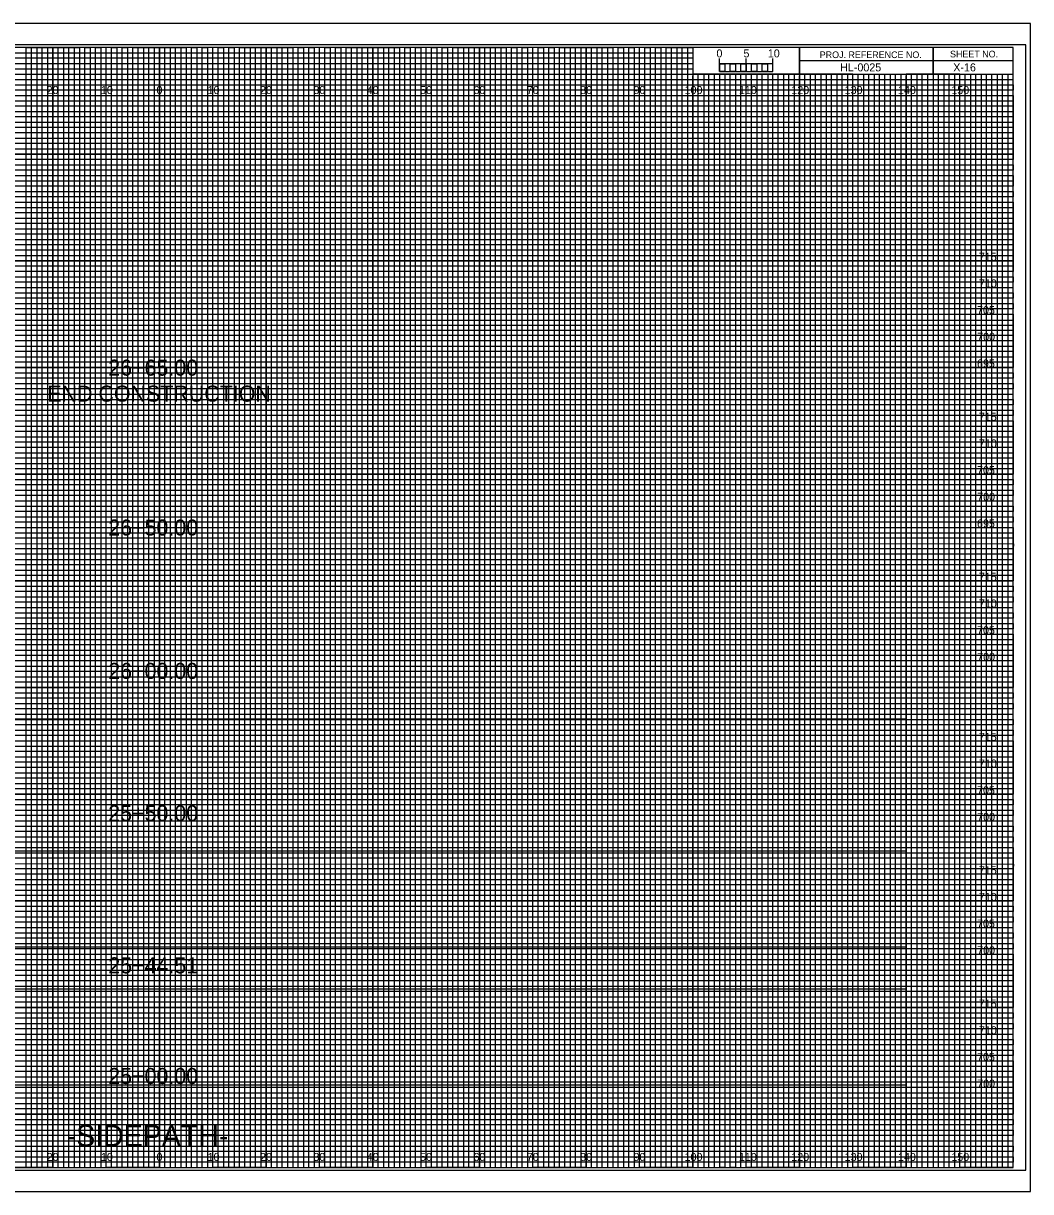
# Model space of a CAD drawing. Extents: x -13 to 323, y -5 to 215.
# Drawn here: x 134.5 to 323.3, y -4.5 to 214.5 of the extents above; entities that cross this region are included whole.
import ezdxf

# ---------------------------------------------------------------- set-up
doc = ezdxf.new("R2010")
doc.units = 0
for name, color, linetype in [('Prop XS Alignment Label', 7, 'Continuous'), ('Prop XS Bar Scale Labels', 7, 'Continuous'), ('Prop XS Elevation Labels', 7, 'Continuous'), ('Prop XS Offset Labels', 7, 'Continuous'), ('Prop XS Project Number', 7, 'Continuous'), ('Prop XS Sheet Number', 7, 'Continuous'), ('Prop XS Station Labels', 7, 'Continuous'), ('Scratch_Level_3', 7, 'Continuous'), ('Sheet Cross Section CELL', 7, 'Continuous'), ('Sheet Cross Section Grid Major CELL', 7, 'Continuous'), ('Sheet Cross Section Grid Middle CELL', 7, 'Continuous'), ('Sheet Cross Section Grid Minor 1 CELL', 7, 'Continuous'), ('Sheet Cross Section Grid Minor 2 CELL', 7, 'Continuous'), ('Sheet Cross Section Scale CELL', 7, 'Continuous'), ('Sheet Cutting Line CELL', 7, 'Continuous'), ('Sheet DOT Grid CELL', 7, 'Continuous'), ('Sheet Plot Border Inside CELL', 7, 'Continuous'), ('Sheet Plot Border Outside CELL', 7, 'Continuous')]:
    doc.layers.add(name, color=color, linetype=linetype)

msp = doc.modelspace()

# ---------------------------------------------------------------- linework, layer by layer
at = {"layer": 'Scratch_Level_3'}
for points in [[(20, 84.12), (300, 84.12), (300, 66.04), (20, 66.04)], [(20, 59.39), (300, 59.39), (300, 41.31), (20, 41.31)], [(20, 33.54), (300, 33.54), (300, 15.46), (20, 15.46)]]:
    msp.add_lwpolyline(points, close=True, dxfattribs=at)
at = {"layer": 'Sheet Cross Section CELL'}
for p, q in [((305, 210), (305, 205)), ((305, 205), (305, 210)), ((280, 207.5), (280, 205)), ((320, 207.49), (280, 207.49)), ((280, 205), (320, 205))]:
    msp.add_line(p, q, dxfattribs=at)
for points in [[(320, 210), (0, 210), (0, 0), (320, 0)], [(280, 210), (260, 210), (260, 205.03), (280, 205.03)], [(320, 210), (280, 210), (280, 205), (320, 205)]]:
    msp.add_lwpolyline(points, close=True, dxfattribs=at)
at = {"layer": 'Sheet Cross Section Grid Major CELL'}
for p, q in [((150, 210), (140, 210)), ((140, 210), (140, 0)), ((150, 0), (150, 210)), ((170, 210), (160, 210)), ((160, 210), (160, 0)), ((170, 0), (170, 210)), ((190, 210), (180, 210)), ((180, 210), (180, 0)), ((190, 0), (190, 210)), ((210, 210), (200, 210)), ((200, 210), (200, 0)), ((210, 0), (210, 210)), ((230, 210), (220, 210)), ((220, 210), (220, 0)), ((230, 0), (230, 210)), ((250, 210), (240, 210)), ((240, 210), (240, 0)), ((250, 0), (250, 210)), ((260, 210), (260, 0)), ((270, 0), (270, 205)), ((290, 205), (280, 205)), ((280, 205), (280, 0)), ((290, 0), (290, 205)), ((310, 205), (300, 205)), ((300, 205), (300, 0)), ((310, 0), (310, 205)), ((140, 0), (130, 0)), ((160, 0), (150, 0)), ((180, 0), (170, 0)), ((200, 0), (190, 0)), ((220, 0), (210, 0)), ((240, 0), (230, 0)), ((260, 0), (250, 0)), ((280, 0), (270, 0)), ((300, 0), (290, 0)), ((320, 0), (310, 0)), ((320, 0), (320, 0))]:
    msp.add_line(p, q, dxfattribs=at)
for points in [[(0, 200), (320, 200), (320, 190), (0, 190)], [(0, 180), (320, 180), (320, 170), (0, 170)], [(0, 160), (320, 160), (320, 150), (0, 150)], [(0, 140), (320, 140), (320, 130), (0, 130)], [(0, 120), (320, 120), (320, 110), (0, 110)], [(0, 100), (320, 100), (320, 90), (0, 90)], [(0, 80), (320, 80), (320, 70), (0, 70)], [(0, 60), (320, 60), (320, 50), (0, 50)], [(0, 40), (320, 40), (320, 30), (0, 30)], [(0, 20), (320, 20), (320, 10), (0, 10)]]:
    msp.add_lwpolyline(points, dxfattribs=at)
at = {"layer": 'Sheet Cross Section Grid Middle CELL'}
for points in [[(125, 0), (135, 0), (135, 210), (145, 210), (145, 0), (155, 0), (155, 210), (165, 210), (165, 0), (175, 0), (175, 210), (185, 210), (185, 0), (195, 0), (195, 210), (205, 210), (205, 0), (215, 0), (215, 210), (225, 210), (225, 0), (235, 0), (235, 210), (245, 210), (245, 0), (255, 0), (255, 210), (259.93, 210), (260, 210), (260, 205), (264.99, 205), (264.99, 0), (275, 0), (275, 205), (285, 205), (285, 0), (295, 0), (295, 205), (305, 205), (305, 0), (315, 0), (315, 205)], [(0, 205), (275, 205)], [(0, 185), (320, 185), (320, 195), (0, 195)], [(0, 165), (320, 165), (320, 175), (0, 175)], [(0, 145), (320, 145), (320, 155), (0, 155)], [(0, 125), (320, 125), (320, 135), (0, 135)], [(0, 105), (320, 105), (320, 115), (0, 115)], [(0, 85), (320, 85), (320, 95), (0, 95)], [(0, 65), (320, 65), (320, 75), (0, 75)], [(0, 45), (320, 45), (320, 55), (0, 55)], [(0, 25), (320, 25), (320, 35), (0, 35)], [(0, 5), (320, 5), (320, 15), (0, 15)]]:
    msp.add_lwpolyline(points, dxfattribs=at)
at = {"layer": 'Sheet Cross Section Grid Minor 1 CELL'}
for p, q in [((0, 209), (260, 209)), ((260, 209), (260, 207.98)), ((260, 207.98), (0, 207.98)), ((0, 207), (260, 207)), ((260, 205.89), (0, 205.89)), ((260, 207), (260, 205.89)), ((0, 204), (320, 204))]:
    msp.add_line(p, q, dxfattribs=at)
for points in [[(0, 203), (270, 203), (320, 203), (320, 202), (0, 202)], [(0, 201), (320, 201), (320, 199), (0, 199)], [(0, 198), (320, 198), (320, 197), (0, 196.98)], [(0, 196), (320, 196), (320, 194), (0, 194)], [(0, 193), (320, 193), (320, 192), (0, 192)], [(0, 191), (320, 191), (320, 189), (0, 189)], [(0, 188), (320, 188), (320, 187), (0, 187)], [(0, 186), (320, 186), (320, 184), (0, 184)], [(0, 183), (320, 183), (320, 182), (0, 182)], [(0, 181), (320, 181), (320, 179), (0, 179)], [(0, 178), (320, 178), (320, 177), (0, 177)], [(0, 176), (320, 176), (320, 173.95), (320, 173), (320, 172), (0, 172)], [(0, 174), (320, 174), (320, 173), (0, 173)], [(0, 171), (320, 171), (320, 169), (0, 169.03)], [(0, 169.03), (320, 169), (320, 168), (0, 168)], [(0, 167), (320, 167), (320, 166), (0, 166)], [(0, 164), (320, 164), (320, 163), (0, 163)], [(0, 162), (320, 162), (320, 161), (0, 161)], [(-0.07, 158.89), (320, 158.89), (320, 157.88), (-0.07, 157.88)], [(0, 157), (320, 157), (320, 156), (0, 156)], [(0, 154), (320, 154), (320, 153), (0, 153)], [(0, 152), (320, 152), (320, 151), (0, 151)], [(0, 149), (320, 149), (320, 148), (0, 148)], [(0, 147), (320, 147), (320, 146), (0, 146)], [(0, 144), (320, 144), (320, 143), (0, 143)], [(0, 142), (320, 142), (320, 141), (0, 141)], [(0, 139), (320, 139), (319.99, 137.98), (0, 138)], [(0, 137), (320, 137), (320, 136), (0, 136)], [(0, 134), (320, 134), (320, 133), (0, 133)], [(0, 132), (320, 132), (320, 131), (0, 131)], [(0, 129), (320, 129), (320, 128), (0, 128)], [(0, 127), (320, 127), (320, 126), (0, 126)], [(0, 124), (320, 124), (320, 123), (0, 123)], [(0, 122), (320, 122), (320, 121), (0, 121)], [(0, 119), (320, 119), (320, 118), (0, 118)], [(0, 116.99), (320.07, 116.91), (320, 116), (0, 116)], [(0, 114), (320, 114), (320, 113), (0, 113)], [(0, 112), (320, 112), (320, 111), (0, 111)], [(0, 109), (320, 109), (320, 108), (0, 108)], [(0, 107), (320, 107), (320, 106), (0, 106)], [(0, 104), (320, 104), (320, 103), (0, 103)], [(0, 102), (320, 102), (320, 101), (0, 101)], [(0, 99), (320, 99), (320, 98), (0, 98)], [(0, 97), (320, 97), (320, 96), (0, 96)], [(0, 94), (320, 94), (320, 93), (0, 93)], [(0, 92), (320, 92), (320, 91), (0, 91)], [(0, 89), (320, 89), (320, 88), (0, 88)], [(0, 87), (320, 87), (320, 86), (0, 86)], [(0, 84), (320, 84), (320, 83), (0, 83)], [(0, 82), (320, 82), (320, 81), (0, 81)], [(0, 79), (320, 79), (319.99, 77.98), (0, 78)], [(0, 77), (320, 77), (320, 76), (0, 76)], [(0, 74), (320, 74), (320, 73), (0, 73)], [(0, 72), (320, 72), (320, 71), (0, 71)], [(0, 69), (320, 69), (320, 68), (0, 68)], [(0, 67), (320, 67), (320, 66), (0, 66)], [(0, 64), (320, 64), (320, 63), (0, 63)], [(0, 62), (320, 62), (320, 61), (0, 61)], [(0, 59), (320, 59), (320, 58), (0, 58)], [(0, 56.99), (320.07, 56.91), (320, 56), (0, 56)], [(0, 54), (320, 54), (320, 53), (0, 53)], [(0, 52), (320, 52), (320, 51), (0, 51)], [(0, 49), (320, 49), (320, 48), (0, 48)], [(0, 47), (320, 47), (320, 46), (0, 46)], [(0, 44), (320, 44), (320, 43), (0, 43)], [(0, 42), (320, 42), (320, 41), (0, 41)], [(0, 39), (320, 39), (320, 38), (0, 38)], [(0, 37), (320, 37), (320, 36), (0, 36)], [(0, 34), (320, 34), (320, 33), (0, 33)], [(0, 32), (320, 32), (320, 31), (0, 31)], [(0, 29), (320, 29), (320, 28), (0, 28)], [(0, 27), (320, 27), (320, 26), (0, 26)], [(0, 24), (320, 24), (320, 23), (0, 23)], [(0, 22), (320, 22), (320, 21), (0, 21)], [(0, 19), (320, 19), (320, 18), (0, 18)], [(0, 17), (320, 17), (320, 16), (0, 16)], [(0, 14), (320, 14), (320, 13), (0, 13)], [(0, 12), (320, 12), (320, 11), (0, 11)], [(0, 9), (320, 9), (320, 8), (0, 8)], [(0, 7), (320, 7), (320, 6), (0, 6)], [(0, 4), (320, 4), (320, 3), (0, 3)], [(0, 2), (320, 2), (320, 1), (0, 1)]]:
    msp.add_lwpolyline(points, dxfattribs=at)
at = {"layer": 'Sheet Cross Section Grid Minor 2 CELL'}
for p, q in [((267, 205), (266.01, 205)), ((266.01, 205), (266.01, 0)), ((267, 0), (267, 205)), ((269, 205), (268, 205)), ((268, 205), (268, 0)), ((269, 0), (269, 205)), ((266.01, 0), (265, 0)), ((268, 0), (267, 0))]:
    msp.add_line(p, q, dxfattribs=at)
for points in [[(135, 0), (136, 0), (136, 210), (137, 210), (137, 0)], [(137, 0), (138, 0), (138, 210), (139, 210), (139, 0)], [(140, 0), (141, 0), (141, 210), (142, 210), (142, 0)], [(142, 0), (143, 0), (143, 210), (144, 210), (144, 0)], [(145, 0), (146, 0), (146, 210), (147, 210), (147, 0)], [(147, 0), (148, 0), (148, 210), (149, 210), (149, 0)], [(150, 0), (151, 0), (151, 210), (152, 210), (152, 0)], [(152, 0), (153, 0), (153, 210), (154, 210), (154, 0)], [(155, 0), (156, 0), (156, 210), (157, 210), (157, 0)], [(157, 0), (158, 0), (158, 210), (159, 210), (159, 0)], [(160, 0), (161, 0), (161, 210), (162, 210), (162, 0)], [(162, 0), (163, 0), (163, 210), (164, 210), (164, 0)], [(165, 0), (166, 0), (166, 210), (167, 210), (167, 0)], [(167, 0), (168, 0), (168, 210), (169, 210), (169, 0)], [(170, 0), (171, 0), (171, 210), (172, 210), (172, 0)], [(172, 0), (173, 0), (173, 210), (174, 210), (174, 0)], [(175, 0), (176, 0), (176, 210), (177, 210), (177, 0)], [(177, 0), (178, 0), (178, 210), (179, 210), (179, 0)], [(180, 0), (181, 0), (181, 210), (182, 210), (182, 0)], [(182, 0), (183, 0), (183, 210), (184, 210), (184, 0)], [(185, 0), (186, 0), (186, 210), (187, 210), (187, 0)], [(187, 0), (188, 0), (188, 210), (189, 210), (189, 0)], [(190, 0), (191, 0), (191, 210), (192, 210), (192, 0)], [(192, 0), (193, 0), (193, 210), (194, 210), (194, 0)], [(195, 0), (196, 0), (196, 210), (197, 210), (197, 0)], [(197, 0), (198, 0), (198, 210), (199, 210), (199, 0)], [(200, 0), (201, 0), (201, 210), (202, 210), (202, 0)], [(202, 0), (203, 0), (203, 210), (204, 210), (204, 0)], [(205, 0), (206, 0), (206, 210), (207, 210), (207, 0)], [(207, 0), (208, 0), (208, 210), (209, 210), (209, 0)], [(210, 0), (211, 0), (211, 210), (212, 210), (212, 0)], [(212, 0), (213, 0), (213, 210), (214, 210), (214, 0)], [(215, 0), (216, 0), (216, 210), (217, 210), (217, 0)], [(217, 0), (218, 0), (218, 210), (219, 210), (219, 0)], [(220, 0), (221, 0), (221, 210), (222, 210), (222, 0)], [(222, 0), (223, 0), (223, 210), (224, 210), (224, 0)], [(225, 0), (226, 0), (226, 210), (227, 210), (227, 0)], [(227, 0), (228, 0), (228, 210), (229, 210), (229, 0)], [(230, 0), (231, 0), (231, 210), (232, 210), (232, 0)], [(232, 0), (233, 0), (233, 210), (234, 210), (234, 0)], [(235, 0), (236, 0), (236, 210), (237, 210), (237, 0)], [(237, 0), (238, 0), (238, 210), (239, 210), (239, 0)], [(240, 0), (241, 0), (241, 210), (242, 210), (242, 0)], [(242, 0), (243, 0), (243, 210), (244, 210), (244, 0)], [(245, 0), (246, 0), (246, 210), (247, 210), (247, 0)], [(247, 0), (248, 0), (248, 210), (249, 210), (249, 0)], [(250, 0), (251, 0), (251, 210), (252, 210), (252, 0)], [(252, 0), (253, 0), (253, 210), (254, 210), (254, 0)], [(255, 0), (256, 0), (256, 210), (257, 210), (257, 0)], [(257, 0), (258, 0), (258, 210), (259, 210), (259, 0)], [(260, 0), (261, 0), (261, 205), (262.02, 205), (262.02, 0)], [(262, 0), (263, 0), (263, 205), (263.99, 205), (263.99, 0)], [(270, 0), (270.98, 0), (270.98, 205), (272, 205), (272, 0)], [(272, 0), (273, 0), (273, 205), (274.05, 205), (274.05, 0)], [(275, 0), (276, 0), (276, 205), (277, 205), (277, 0)], [(277, 0), (278, 0), (278, 205), (279, 205), (279, 0)], [(280, 0), (281, 0), (281, 205), (282, 205), (282, 0)], [(282, 0), (283, 0), (283, 205), (284, 205), (284, 0)], [(285, 0), (286, 0), (286, 205), (287, 205), (287, 0)], [(287, 0), (288, 0), (288, 205), (289, 205), (289, 0)], [(290, 0), (291, 0), (291, 205), (292, 205), (292, 0)], [(292, 0), (293, 0), (293, 205), (294, 205), (294, 0)], [(295, 0), (296, 0), (296, 205), (297, 205), (297, 0)], [(297, 0), (298, 0), (298, 205), (299, 205), (299, 0)], [(300, 0), (301, 0), (301, 205), (302, 205), (302, 0)], [(302, 0), (303, 0), (303, 205), (304, 205), (304, 0)], [(305, 0), (306, 0), (306, 205), (307, 205), (307, 0)], [(307, 0), (308, 0), (308, 205), (309, 205), (309, 0)], [(310, 0), (311, 0), (311, 205), (312, 205), (312, 0)], [(312, 0), (313, 0), (313, 205), (314, 205), (314, 0)], [(315, 0), (316, 0), (316, 205), (317, 205), (317, 0)], [(317, 0), (318, 0), (318, 205), (319, 205), (319, 0)]]:
    msp.add_lwpolyline(points, dxfattribs=at)
at = {"layer": 'Sheet Cross Section Scale CELL'}
for p, q in [((265, 205.49), (265, 207.9)), ((265, 206.9), (265, 207.9)), ((270, 205.49), (270, 207.9)), ((275, 205.49), (275, 207.9)), ((275, 206.9), (275, 207.9))]:
    msp.add_line(p, q, dxfattribs=at)
for points in [[(275, 206.9), (265, 206.9), (265, 205.49), (275, 205.49)], [(265, 206.9), (266, 206.9), (266, 205.49), (265, 205.49)], [(267, 206.9), (268, 206.9), (268, 205.49), (267, 205.49)], [(269, 206.9), (270, 206.9), (270, 205.49), (269, 205.49)], [(271, 206.9), (272, 206.9), (272, 205.49), (271, 205.49)], [(273, 206.9), (274, 206.9), (274, 205.49), (273, 205.49)]]:
    msp.add_lwpolyline(points, close=True, dxfattribs=at)
at = {"layer": 'Sheet Cutting Line CELL'}
for p, q in [((323.3, 214.5), (-13.4, 214.5)), ((-13.4, -4.5), (323.3, -4.5))]:
    msp.add_line(p, q, dxfattribs=at)
at = {"layer": 'Sheet DOT Grid CELL'}
for p, q in [((140, 0), (140, 210)), ((150, 0), (150, 210)), ((160, 0), (160, 210)), ((170, 0), (170, 210)), ((180, 0), (180, 210)), ((190, 0), (190, 210)), ((200, 0), (200, 210)), ((210, 0), (210, 210)), ((220, 0), (220, 210)), ((230, 0), (230, 210)), ((240, 0), (240, 210)), ((250, 0), (250, 210)), ((260, 0), (260, 204.69)), ((270, 0), (270, 204.69)), ((280, 0), (280, 204.69)), ((290, 0), (290, 204.69)), ((300, 0), (300, 204.69)), ((310, 0), (310, 204.69)), ((0, 200), (320, 200)), ((0, 190), (320, 190)), ((0, 180), (320, 180)), ((0, 170), (320, 170)), ((0, 160), (320, 160)), ((0, 150), (320, 150)), ((0, 140), (320, 140)), ((0, 130), (320, 130)), ((0, 120), (320, 120)), ((0, 110), (320, 110)), ((0, 100), (320, 100)), ((0, 90), (320, 90)), ((0, 80), (320, 80)), ((0, 70), (320, 70)), ((0, 60), (320, 60)), ((0, 50), (320, 50)), ((0, 40), (320, 40)), ((0, 30), (320, 30)), ((0, 20), (320, 20)), ((0, 10), (320, 10))]:
    msp.add_line(p, q, dxfattribs=at)
at = {"layer": 'Sheet Plot Border Inside CELL'}
msp.add_lwpolyline([(-10.8, -0.5), (322.4, -0.5), (322.4, 210.5), (-10.8, 210.5)], close=True, dxfattribs=at)
at = {"layer": 'Sheet Plot Border Outside CELL'}
msp.add_lwpolyline([(-13.4, -4.5), (323.3, -4.5), (323.3, 214.5), (-13.4, 214.5)], close=True, dxfattribs=at)

# ---------------------------------------------------------------- texts
at = {"layer": 'Prop XS Alignment Label'}
msp.add_text('-SIDEPATH-', height=4, dxfattribs=at).set_placement((142.62, 4))
at = {"layer": 'Prop XS Bar Scale Labels'}
for s, p in [('5', (269.47, 208.12)), ('10', (274.04, 208.12))]:
    msp.add_text(s, height=1.5, dxfattribs=at).set_placement(p)
at = {"layer": 'Prop XS Elevation Labels'}
for s, p in [('715', (313.59, 170)), ('710', (313.61, 165)), ('705', (313.26, 160)), ('700', (313.28, 155)), ('695', (313.25, 150)), ('715', (313.59, 140)), ('710', (313.61, 135)), ('705', (313.26, 130)), ('700', (313.28, 125)), ('695', (313.25, 120)), ('715', (313.59, 110)), ('710', (313.61, 105)), ('705', (313.26, 100)), ('700', (313.28, 95)), ('715', (313.59, 80)), ('710', (313.61, 75)), ('705', (313.26, 70)), ('700', (313.28, 65)), ('715', (313.59, 55)), ('710', (313.61, 50)), ('705', (313.26, 45)), ('700', (313.28, 40)), ('715', (313.59, 30)), ('710', (313.61, 25)), ('705', (313.26, 20)), ('700', (313.28, 15))]:
    msp.add_text(s, height=1.5, dxfattribs=at).set_placement(p)
at = {"layer": 'Prop XS Offset Labels'}
for s, p in [('20', (138.86, 201.25)), ('10', (149.04, 201.25)), ('0', (159.45, 201.25)), ('0', (159.45, 201.25)), ('10', (169.04, 201.25)), ('20', (178.86, 201.25)), ('30', (188.86, 201.25)), ('40', (198.86, 201.25)), ('50', (208.86, 201.25)), ('60', (218.86, 201.25)), ('70', (228.86, 201.25)), ('80', (238.86, 201.25)), ('90', (248.86, 201.25)), ('100', (258.44, 201.25)), ('110', (268.62, 201.25)), ('120', (278.44, 201.25)), ('130', (288.44, 201.25)), ('140', (298.44, 201.25)), ('150', (308.44, 201.25)), ('20', (138.86, 1.25)), ('10', (149.04, 1.25)), ('0', (159.45, 1.25)), ('0', (159.45, 1.25)), ('10', (169.04, 1.25)), ('20', (178.86, 1.25)), ('30', (188.86, 1.25)), ('40', (198.86, 1.25)), ('50', (208.86, 1.25)), ('60', (218.86, 1.25)), ('70', (228.86, 1.25)), ('80', (238.86, 1.25)), ('90', (248.86, 1.25)), ('100', (258.44, 1.25)), ('110', (268.62, 1.25)), ('120', (278.44, 1.25)), ('130', (288.44, 1.25)), ('140', (298.44, 1.25)), ('150', (308.44, 1.25))]:
    msp.add_text(s, height=1.5, dxfattribs=at).set_placement(p)
at = {"layer": 'Prop XS Project Number'}
msp.add_text('HL-0025', height=1.5, dxfattribs=at).set_placement((287.6, 205.5))
at = {"layer": 'Prop XS Sheet Number'}
msp.add_text('X-16', height=1.5, dxfattribs=at).set_placement((308.8, 205.5))
at = {"layer": 'Prop XS Station Labels'}
for s, p in [('26+65.00', (150.41, 148.46)), ('END CONSTRUCTION', (138.99, 143.59)), ('26+50.00', (150.41, 118.49)), ('26+00.00', (150.41, 91.61)), ('25+50.00', (150.41, 64.93)), ('25+44.51', (150.42, 36.42)), ('25+00.00', (150.41, 15.68))]:
    msp.add_text(s, height=3, dxfattribs=at).set_placement(p)
at = {"layer": 'Sheet Cross Section CELL'}
for s, p in [('PROJ. REFERENCE NO.', (283.77, 207.99)), ('SHEET NO.', (308.19, 208.12))]:
    msp.add_text(s, height=1.25, dxfattribs=at).set_placement(p)
at = {"layer": 'Sheet Cross Section Scale CELL'}
msp.add_text('0', height=1.5, dxfattribs=at).set_placement((264.41, 208.12))

doc.saveas('drawing.dxf')
